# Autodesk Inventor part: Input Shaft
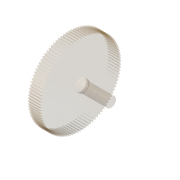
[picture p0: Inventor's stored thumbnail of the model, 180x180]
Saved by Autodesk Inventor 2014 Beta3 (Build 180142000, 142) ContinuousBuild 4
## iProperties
Created: 2011-01
Part Number: Input Shaft
Material: Steel
Document SubType Name: Modeling
Designer: Beta-8540w
Density: 1 g/cm^3
Appearance: Polycarbonate - Smoked
CustomPartVersion: 1
Author: Beta-8540w
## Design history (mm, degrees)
sketch "Main Sketch"
  geometry: L1 (0, 0)-(43, 0) reference; L2 (0, 0)-(0, 45); L3 (12, 45)-(12, 6); L4 (0, 45)-(12, 45); L5 (15, 6)-(15, 5); L6 (12, 6)-(15, 6); L7 (43, 5)-(43, 0); L8 (15, 5)-(43, 5)
  constraints: 16 end point, 5 horizontal, 4 vertical
  dimensions: "d3" = 90 diameter of L4 L1 (derived); "d4" = 12 diameter of L6 L1 (derived); "d5" = 10 diameter of L8 L1 (derived)
revolve "Revolution1" sketch "Main Sketch" stored, may be unused: angle "d6" = 0 deg
chamfer "Chamfer1" distance "d7" = 0.5; stored, may be unused: second distance "d8" = 0.125, angle "d9" = 45 deg
node "Retaining Ring Groove1"
node "Spur Gear Teeth2"
body "Solid1"
feature "iFeature27:1"
feature "Spur Gear Feature 2"
other parameters: "d0" = 0, "d1" = 0, "d2" = 0
